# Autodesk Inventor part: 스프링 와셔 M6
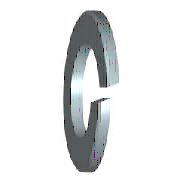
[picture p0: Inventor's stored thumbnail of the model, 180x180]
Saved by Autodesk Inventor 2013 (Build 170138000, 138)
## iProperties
IsCustomPart: 1
Created: 2012-02
Part Number: 스프링 와셔 M6
Material: 강철, 연강
Description: 스프링 와셔
Document SubType Name: Modeling
Standard: JIS B 1251
Designer: mdu-01
Standards Organization: JIS
Language: ko-KR
Size Designation: 번호 2 6
Categories: <MemberInstance><Categories><Category DisplayName="조임쇠" InternalName="e4da775c-781d-43d5-af7c-5136215cf5a6" Mnemonic="FSTN"><Category DisplayName="와셔" InternalN
Density: 7.86 g/cm^3
Mass: 1.01202 g
Surface Area: 2.65887 cm^2
Volume: 0.128756 cm^3
Author: mdu-01
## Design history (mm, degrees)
sketch "스케치1"
  geometry: C1 r 6.1 at (0, 0); C2 r 3.05 at (0, 0); 1 further point
  constraints: 2 centre point, 2 coincident
  dimensions: "d0" = 6.1 diameter of C2 (= SD1); "d1" = 12.2 diameter of C1 (= SD2)
extrude "본체" new body sketch "스케치1" distance "d2" = 1.5 (= SD); taper "d3" = 0 deg
sketch "스케치2"
  geometry: L1 (0, -3.05)-(0, 3.05) reference; L2 (1.5, 6.1)-(1.5, -6.1) reference; L3 (-1.2, 0)-(7.2, 0) reference; L4 (0, -0.3)-(1.5, 0.246); L5 (0, 0.3)-(1.5, 0.846)
  constraints: 4 end point, 4 point on line, 1 parallel
  dimensions: "d4" = 0.3 distance from line of L3 L4.start (= 0.2 x SD); "d5" = 0.3 distance from line of L3 L5.start (= 0.2 x SD); "d6" = 70 deg angle of L2 L4 (= FAWI)
extrude "절단부" cut sketch "스케치2" stored distance "d7" = 1.5 (= SD); taper "d8" = 0 deg
workaxis "Work Axis1"
workplane "Work Plane1"
body "Solid1"
other parameters: "SD1" = 6.1 [user parameter; used in 1 equation term], "SD2" = 12.2 [user parameter; used in 1 equation term], "SD" = 1.5 [user parameter; used in 4 equation terms], "FAWI" = 70 deg [user parameter; used in 1 equation term], "d9" = 0, "d10" = 0, "d11" = 0, "d12" = 0, "SDI" = 2.7 [user parameter], "NND" = 6 [user parameter]
